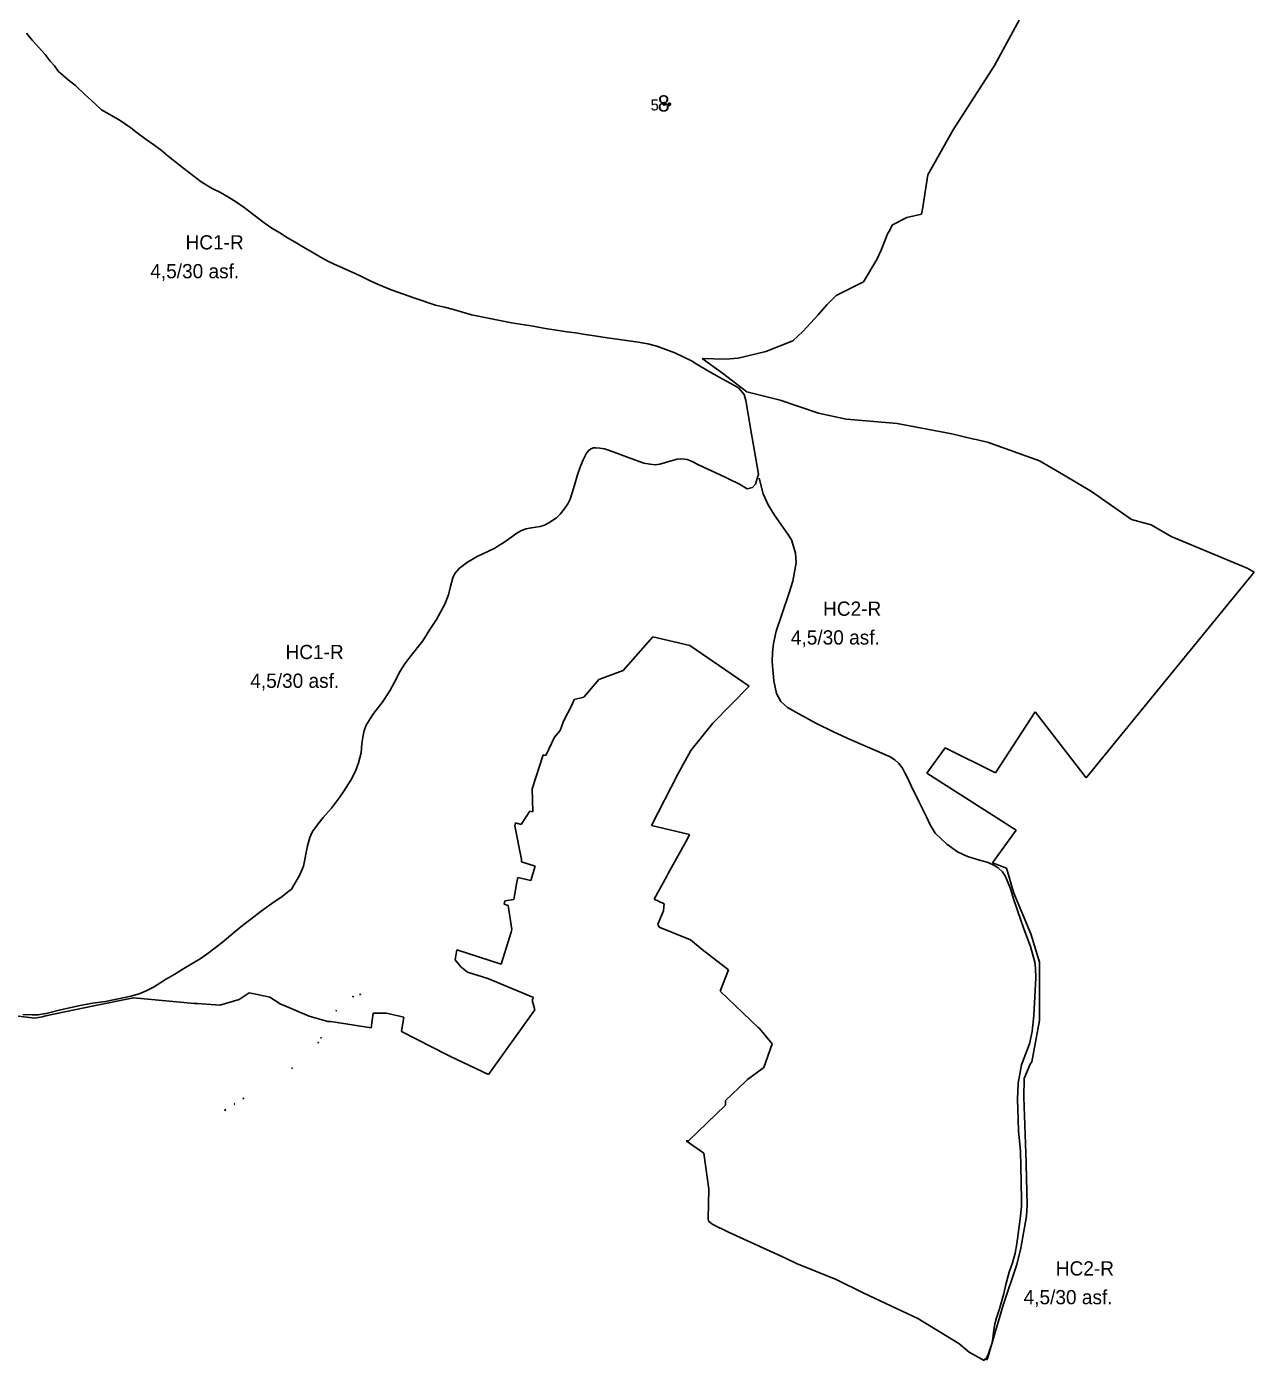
# Model space of a CAD drawing. Extents: x -543464 to -538545, y -1098769 to -1093672.
# Drawn here: x -540442 to -538545, y -1098552 to -1096492 of the extents above; entities that cross this region are included whole.
import ezdxf

# ---------------------------------------------------------------- set-up
doc = ezdxf.new("R2010")
doc.units = 0
for name, color, linetype in [('00_CHMI', 7, 'Continuous'), ('00_IGP_sondy', 7, 'Continuous'), ('01_OBVOD PÚ', 7, 'Continuous'), ('03_PC_NAVRH', 7, 'Continuous'), ('03_PC_POPIS_NAVRH', 7, 'Continuous'), ('07_VODOVOD', 7, 'Continuous')]:
    doc.layers.add(name, color=color, linetype=linetype)

msp = doc.modelspace()

# ---------------------------------------------------------------- linework, layer by layer
at = {"layer": '00_CHMI'}
for p, q in [((-539454.5, -1096611.1), (-539459.5, -1096611.1)), ((-539457, -1096613.5), (-539457, -1096608.8)), ((-539457, -1096611.1), (-539457, -1096611.1))]:
    msp.add_line(p, q, dxfattribs=at)
msp.add_circle((-539457, -1096611.1), 2, dxfattribs=at)
at = {"layer": '00_IGP_sondy'}
for p, q in [((-539446.6, -1096612), (-539451.6, -1096612)), ((-539449.1, -1096614.3), (-539449.1, -1096609.6)), ((-539449.1, -1096612), (-539449.1, -1096612))]:
    msp.add_line(p, q, dxfattribs=at)
msp.add_circle((-539449.1, -1096612), 2, dxfattribs=at)
at = {"layer": '01_OBVOD PÚ'}
for p, q in [((-538946.8, -1096551.9), (-538908.6, -1096482.2)), ((-539010.8, -1096651.4), (-538946.8, -1096551.9)), ((-539049.7, -1096721.1), (-539010.8, -1096651.4)), ((-539058.2, -1096773.9), (-539049.7, -1096721.1)), ((-539082.5, -1096786.7), (-539059.5, -1096781.4)), ((-539059.5, -1096781.4), (-539058.2, -1096773.9)), ((-539110.2, -1096808.8), (-539104.2, -1096797.9)), ((-539104.2, -1096797.9), (-539082.5, -1096786.7)), ((-539122.1, -1096837.3), (-539111.5, -1096811.1)), ((-539111.5, -1096811.1), (-539110.2, -1096808.8)), ((-539128.7, -1096851.5), (-539122.1, -1096837.3)), ((-539149.4, -1096885.9), (-539128.7, -1096851.5)), ((-539191.3, -1096907.2), (-539149.4, -1096885.9)), ((-539206.1, -1096921.4), (-539191.3, -1096907.2)), ((-539219.2, -1096936.8), (-539206.1, -1096921.4)), ((-539242.7, -1096962.7), (-539219.2, -1096936.8)), ((-539258.6, -1096977.3), (-539242.7, -1096962.7)), ((-539300, -1096993.8), (-539258.6, -1096977.3)), ((-539367, -1097027.2), (-539398.5, -1097004.4)), ((-539398.5, -1097004.4), (-539362.9, -1097005.6)), ((-539362.9, -1097005.6), (-539343, -1097004.1)), ((-539343, -1097004.1), (-539300, -1096993.8)), ((-539329.7, -1097056), (-539367, -1097027.2)), ((-539278.2, -1097068.7), (-539329.7, -1097056)), ((-539218.5, -1097088.8), (-539278.2, -1097068.7)), ((-539176.1, -1097098), (-539218.5, -1097088.8)), ((-539169.2, -1097098.9), (-539176.1, -1097098)), ((-539097.2, -1097104.9), (-539169.2, -1097098.9)), ((-539012.8, -1097120.8), (-539097.2, -1097104.9)), ((-538978.7, -1097128.8), (-539012.8, -1097120.8)), ((-538975.3, -1097129.6), (-538978.7, -1097128.8)), ((-538956.1, -1097134.1), (-538975.3, -1097129.6)), ((-538877.1, -1097162.4), (-538956.1, -1097134.1)), ((-538735.3, -1097253.1), (-538797.2, -1097209.7)), ((-538705, -1097261.1), (-538735.3, -1097253.1)), ((-538673.7, -1097279.6), (-538705, -1097261.1)), ((-538556.7, -1097328.1), (-538673.7, -1097279.6)), ((-538669.6, -1097486.2), (-538545.5, -1097334.4)), ((-538545.5, -1097334.4), (-538556.7, -1097328.1)), ((-539520.5, -1097486.2), (-539474.7, -1097434.5)), ((-539474.7, -1097434.5), (-539417.7, -1097447.8)), ((-539417.7, -1097447.8), (-539325.8, -1097510.3)), ((-539557.9, -1097500.1), (-539520.5, -1097486.2)), ((-538805.1, -1097652.1), (-538669.6, -1097486.2)), ((-539581, -1097527.5), (-539557.9, -1097500.1)), ((-539596.3, -1097530.9), (-539581, -1097527.5)), ((-539325.8, -1097510.3), (-539382.1, -1097567.6)), ((-539612.9, -1097564.4), (-539599.9, -1097539.6)), ((-539599.9, -1097539.6), (-539596.3, -1097530.9)), ((-539617.9, -1097579.2), (-539612.9, -1097564.4)), ((-539382.1, -1097567.6), (-539416, -1097609.7)), ((-538945.4, -1097644.3), (-538883.8, -1097550.2)), ((-538883.8, -1097550.2), (-538810.3, -1097645.3)), ((-539640.2, -1097617.5), (-539626.7, -1097589.2)), ((-539626.7, -1097589.2), (-539617.9, -1097579.2)), ((-539416, -1097609.7), (-539435.9, -1097646.6)), ((-539051.3, -1097644.6), (-539023.3, -1097605.5)), ((-539023.3, -1097605.5), (-538945.4, -1097644.3)), ((-539661.1, -1097668.9), (-539643.9, -1097616.4)), ((-539643.9, -1097616.4), (-539640.2, -1097617.5)), ((-539435.9, -1097646.6), (-539476.7, -1097725.6)), ((-538913.4, -1097733), (-539051.3, -1097644.6)), ((-538810.3, -1097645.3), (-538805.1, -1097652.1)), ((-539660.2, -1097704.7), (-539661.1, -1097668.9)), ((-539678.2, -1097724.2), (-539664.7, -1097703.4)), ((-539664.7, -1097703.4), (-539660.2, -1097704.7)), ((-539687.7, -1097726.1), (-539686.8, -1097721.3)), ((-539677.3, -1097777.9), (-539687.7, -1097726.1)), ((-539686.8, -1097721.3), (-539678.2, -1097724.2)), ((-539476.7, -1097725.6), (-539417.8, -1097739.7)), ((-538949.8, -1097783.5), (-538913.4, -1097733)), ((-539420.8, -1097745.2), (-539451.1, -1097799.9)), ((-539417.8, -1097739.7), (-539420.8, -1097745.2)), ((-539677.4, -1097782), (-539677.3, -1097777.9)), ((-539656.6, -1097788.7), (-539677.4, -1097782)), ((-539663.3, -1097810.6), (-539656.6, -1097788.7)), ((-538928.2, -1097791.6), (-538949.8, -1097783.5)), ((-538926.8, -1097796.5), (-538928.2, -1097791.6)), ((-539689.2, -1097839.9), (-539684.8, -1097813.1)), ((-539684.8, -1097813.1), (-539683.1, -1097806)), ((-539683.1, -1097806), (-539663.3, -1097810.6)), ((-539453.2, -1097803.8), (-539472.8, -1097839.3)), ((-539451.1, -1097799.9), (-539453.2, -1097803.8)), ((-538917.2, -1097830.2), (-538926.8, -1097796.5)), ((-538890.6, -1097892.9), (-538917.2, -1097830.2)), ((-539704.1, -1097847), (-539703.5, -1097841.9)), ((-539698.3, -1097849.4), (-539704.1, -1097847)), ((-539703.5, -1097841.9), (-539689.2, -1097839.9)), ((-539692.3, -1097886.3), (-539698.3, -1097849.4)), ((-539472.8, -1097839.3), (-539457.3, -1097846.8)), ((-539457.6, -1097851), (-539458, -1097857.2)), ((-539457.3, -1097846.8), (-539457.6, -1097851)), ((-539458, -1097857.2), (-539466.8, -1097877.9)), ((-539708.8, -1097939.7), (-539693.5, -1097890.2)), ((-539693.5, -1097890.2), (-539692.3, -1097886.3)), ((-539466.8, -1097877.9), (-539465, -1097882.7)), ((-539465, -1097882.7), (-539416.6, -1097902.1)), ((-538877.1, -1097936.9), (-538890.6, -1097892.9)), ((-539780.2, -1097933), (-539777.3, -1097917.9)), ((-539777.3, -1097917.9), (-539708.8, -1097939.7)), ((-539416.6, -1097902.1), (-539398.4, -1097917.3)), ((-539398.4, -1097917.3), (-539358, -1097948.6)), ((-539771.4, -1097944.1), (-539780.2, -1097933)), ((-538877.3, -1098026.7), (-538877.1, -1097936.9)), ((-539761.2, -1097952), (-539771.4, -1097944.1)), ((-539729.6, -1097961.9), (-539761.2, -1097952)), ((-539358, -1097948.6), (-539370.8, -1097981.4)), ((-539659.1, -1097991.5), (-539729.6, -1097961.9)), ((-540338.2, -1098004.2), (-540276.8, -1097991.9)), ((-540276.8, -1097991.9), (-540182.9, -1098000.4)), ((-540182.9, -1098000.4), (-540178.1, -1098000.6)), ((-540178.1, -1098000.6), (-540143.4, -1098003.2)), ((-540143.4, -1098003.2), (-540113.6, -1097994.1)), ((-540113.6, -1097994.1), (-540098.1, -1097984.3)), ((-540098.1, -1097984.3), (-540085.5, -1097986.8)), ((-540085.5, -1097986.8), (-540083.5, -1097987.2)), ((-540083.5, -1097987.2), (-540066.4, -1097990.7)), ((-540066.4, -1097990.7), (-540050.4, -1098001)), ((-540050.4, -1098001), (-540005.7, -1098019.9)), ((-539661.1, -1097995.2), (-539659.1, -1097991.5)), ((-539657.1, -1098010.2), (-539661.1, -1097995.2)), ((-539370.8, -1097981.4), (-539311.9, -1098037.5)), ((-540471.6, -1098018), (-540429.4, -1098023.4)), ((-540429.4, -1098023.4), (-540418.1, -1098021)), ((-540418.1, -1098021), (-540410.1, -1098019.3)), ((-540410.1, -1098019.3), (-540338.2, -1098004.2)), ((-540005.7, -1098019.9), (-539976.6, -1098028.4)), ((-539909.8, -1098038.1), (-539906.9, -1098015.4)), ((-539906.9, -1098015.4), (-539886.1, -1098015.3)), ((-539886.1, -1098015.3), (-539859.5, -1098021.7)), ((-539859.5, -1098021.7), (-539863.1, -1098043.7)), ((-539728.4, -1098110.3), (-539657.1, -1098010.2)), ((-539971.9, -1098028.5), (-539909.8, -1098038.1)), ((-539311.9, -1098037.5), (-539309.9, -1098038.9)), ((-539309.9, -1098038.9), (-539290.1, -1098062.6)), ((-538889.4, -1098090.5), (-538877.3, -1098026.7)), ((-539863.1, -1098043.7), (-539792.5, -1098080)), ((-539290.1, -1098062.6), (-539303.4, -1098099.5)), ((-539792.5, -1098080), (-539787.1, -1098082.6)), ((-539787.1, -1098082.6), (-539728.4, -1098110.3)), ((-539303.4, -1098099.5), (-539328.3, -1098117.7)), ((-538901, -1098116.5), (-538891.8, -1098094.1)), ((-538891.8, -1098094.1), (-538889.4, -1098090.5)), ((-539331.1, -1098120.3), (-539362.4, -1098150.3)), ((-539328.3, -1098117.7), (-539331.1, -1098120.3)), ((-538901.3, -1098145.3), (-538901, -1098116.5)), ((-538898.1, -1098245.9), (-538901.3, -1098145.3)), ((-539362.6, -1098157.7), (-539419.2, -1098211.9)), ((-539362.4, -1098150.3), (-539362.6, -1098157.7)), ((-539419.2, -1098211.9), (-539423.4, -1098212.6)), ((-539423.4, -1098212.6), (-539396.1, -1098231.6)), ((-539396.1, -1098231.6), (-539388.4, -1098287)), ((-538898.1, -1098249.4), (-538898.1, -1098245.9)), ((-538896.4, -1098312.1), (-538898.1, -1098249.4)), ((-539388.4, -1098287), (-539389.3, -1098332.6)), ((-538906, -1098378.3), (-538897.3, -1098328.9)), ((-538897.3, -1098328.9), (-538896.4, -1098312.1)), ((-539389.3, -1098332.6), (-539388.9, -1098336.9)), ((-539388.9, -1098336.9), (-539381.9, -1098341.6)), ((-539381.9, -1098341.6), (-539357.7, -1098353.8)), ((-539357.7, -1098353.8), (-539269.6, -1098393.6)), ((-538912.2, -1098403.5), (-538906, -1098378.3)), ((-539269.6, -1098393.6), (-539252.7, -1098401.9)), ((-539252.7, -1098401.9), (-539191.5, -1098426.9)), ((-538933.5, -1098466.4), (-538912.2, -1098403.5)), ((-539191.5, -1098426.9), (-539148.6, -1098448.1)), ((-539148.6, -1098448.1), (-539065.3, -1098486.9)), ((-538957.7, -1098548.6), (-538933.5, -1098466.4)), ((-539065.3, -1098486.9), (-539002.2, -1098525.6)), ((-539002.2, -1098525.6), (-538985.8, -1098539)), ((-538985.8, -1098539), (-538963, -1098551.6)), ((-538963, -1098551.6), (-538961.6, -1098549)), ((-538958.6, -1098550.7), (-538957.7, -1098548.6))]:
    msp.add_line(p, q, dxfattribs=at)
for points in [[(-538797.2, -1097209.7), (-538840.5, -1097184), (-538877.1, -1097162.4)], [(-539976.6, -1098028.4), (-539973.8, -1098028.5), (-539971.9, -1098028.5)], [(-538961.6, -1098549), (-538960, -1098549.9), (-538958.6, -1098550.7)]]:
    msp.add_lwpolyline(points, dxfattribs=at)
at = {"layer": '03_PC_NAVRH'}
for points in [[(-540442.4, -1096501.9), (-540433.2, -1096512.9), (-540413.3, -1096534.8), (-540405.8, -1096545.3), (-540399, -1096552.6), (-540393.1, -1096560.6), (-540377.7, -1096574.1), (-540366.6, -1096583.1), (-540351.6, -1096597.1), (-540342.5, -1096605.6), (-540326.5, -1096620.4), (-540307.3, -1096631.4), (-540297.6, -1096637), (-540281.1, -1096648.3), (-540271.2, -1096656), (-540257.3, -1096666.1), (-540245.3, -1096674.7), (-540234.4, -1096683), (-540223.6, -1096692.2), (-540199.1, -1096711.1), (-540172.4, -1096731.6), (-540155.2, -1096741.8), (-540142.4, -1096748), (-540130, -1096755.6), (-540117.6, -1096763.1), (-540106.1, -1096771.4), (-540090.7, -1096783.3), (-540075, -1096795), (-540063.3, -1096803.1), (-540050.7, -1096810.6), (-540039, -1096817.9), (-540027.2, -1096824.9), (-540015.5, -1096832), (-540003.5, -1096838.9), (-539986.8, -1096848.5), (-539974.6, -1096855.1), (-539962.1, -1096860.7), (-539949.2, -1096866.5), (-539927.6, -1096876.2), (-539910.3, -1096884.9), (-539897.3, -1096890.7), (-539878.7, -1096898.2), (-539842.2, -1096911.2), (-539810.2, -1096922), (-539796.6, -1096925.3), (-539782.5, -1096928.7), (-539754.6, -1096936.9), (-539726.2, -1096942.8), (-539692.9, -1096949.6), (-539659.5, -1096954.8), (-539640.9, -1096958.3), (-539627, -1096960.3), (-539607.4, -1096963.1), (-539593.6, -1096965.1), (-539579.1, -1096967.4), (-539564.7, -1096969.7), (-539545.4, -1096972.4), (-539526.1, -1096975.2), (-539511.7, -1096977.3), (-539497.2, -1096979.3), (-539482.5, -1096982), (-539468.3, -1096985.6), (-539454.7, -1096990.4), (-539440.9, -1096995.8), (-539427.8, -1097001.8), (-539414.8, -1097008.2), (-539407.5, -1097012.9), (-539388.7, -1097024.1), (-539372.4, -1097033.3), (-539355.2, -1097042.8), (-539342.4, -1097049.8), (-539333.4, -1097059.9), (-539331, -1097069.4), (-539327.3, -1097090.5), (-539323.1, -1097114.9), (-539319.7, -1097136), (-539311.5, -1097182.9), (-539316, -1097198.4)], [(-539316, -1097198.4), (-539320.6, -1097203.6), (-539328.7, -1097205.6), (-539340.6, -1097198.7), (-539357.7, -1097190.3), (-539364.2, -1097187.2), (-539389.5, -1097175.3), (-539405.1, -1097168.3), (-539414, -1097163.5), (-539421.4, -1097160.7), (-539430.1, -1097159.5), (-539437.1, -1097159.8), (-539446.1, -1097162.5), (-539464, -1097167.7), (-539471.1, -1097168.5), (-539479, -1097167.7), (-539488.4, -1097165.9), (-539498.1, -1097162.5), (-539511.1, -1097158), (-539531.7, -1097150.2), (-539541.4, -1097146.5), (-539549.3, -1097144), (-539556.3, -1097142.9), (-539562.7, -1097142.3), (-539566.1, -1097142.6), (-539570.3, -1097144), (-539573.7, -1097146.5), (-539577.1, -1097150.9), (-539582.3, -1097161), (-539586.2, -1097170.8), (-539590.9, -1097184.2), (-539595.7, -1097200.2), (-539599.2, -1097211.9), (-539602.6, -1097221.6), (-539606, -1097229), (-539611.4, -1097237.1), (-539618, -1097244.8), (-539623.4, -1097250.3), (-539635.4, -1097258.3), (-539641.9, -1097261.7), (-539648.9, -1097263.9), (-539662, -1097265.8), (-539671, -1097267.5), (-539678.5, -1097270.5), (-539686.3, -1097275.1), (-539692.6, -1097280), (-539706.3, -1097289.9), (-539712.4, -1097293.5), (-539718.5, -1097297.2), (-539728.5, -1097301.9), (-539745.8, -1097310.1), (-539760.9, -1097319.1), (-539765.2, -1097321.9), (-539773.1, -1097328.1), (-539780.3, -1097336.5), (-539783.7, -1097343.4), (-539787, -1097356.4), (-539790.2, -1097369.4), (-539796.1, -1097383.9), (-539808.9, -1097407.4), (-539818.9, -1097423), (-539830.1, -1097440.5), (-539850.2, -1097465.7), (-539857.9, -1097476), (-539865.1, -1097487.4), (-539873.8, -1097504.5), (-539881.1, -1097517.9), (-539892.9, -1097535.5), (-539901.8, -1097547.3), (-539907.2, -1097554.4), (-539917.4, -1097570.6), (-539920.8, -1097578.9), (-539922.8, -1097589.2), (-539924.1, -1097599.6), (-539925.2, -1097613.2), (-539929.3, -1097629), (-539934.1, -1097641.8), (-539941.1, -1097655.4), (-539952, -1097672.8), (-539958.7, -1097682.6), (-539971.2, -1097698.9), (-539983.7, -1097713.4), (-539991.5, -1097722.9), (-540000.2, -1097735.1), (-540004.5, -1097744.3), (-540008.2, -1097757.1), (-540014.5, -1097788.6), (-540020.3, -1097803), (-540033, -1097823.9), (-540037.2, -1097827.2), (-540049.2, -1097836.6), (-540059.5, -1097843.6), (-540079.8, -1097858.2), (-540095.6, -1097870.2), (-540108.7, -1097880.2), (-540120.1, -1097889.6), (-540140.1, -1097906.2), (-540163.7, -1097924.1), (-540174.1, -1097931.5), (-540199.1, -1097946.7), (-540213.2, -1097955.2), (-540227.3, -1097963.7), (-540246.2, -1097975.1), (-540257.4, -1097981.1), (-540268.3, -1097985.6), (-540281.2, -1097989.2), (-540298.2, -1097992.7), (-540320.4, -1097997.2), (-540340.3, -1098000.2), (-540359.2, -1098003.5), (-540389.8, -1098010.3), (-540409.8, -1098015.4), (-540415.3, -1098016.7), (-540424.7, -1098018.1), (-540433.7, -1098018.2), (-540448.1, -1098017.5)], [(-539310.6, -1097189.5), (-539304.2, -1097213.6), (-539296.6, -1097230.6), (-539286.9, -1097246.6), (-539265.9, -1097275.9), (-539260.6, -1097284.7), (-539258.3, -1097291.1), (-539254.4, -1097305), (-539253.1, -1097320), (-539258.2, -1097348.2), (-539263.9, -1097366.2), (-539274.9, -1097398.5), (-539283.9, -1097425.6), (-539288.5, -1097444.8), (-539290, -1097458.6), (-539290.3, -1097472.9), (-539287.9, -1097502.1), (-539283.7, -1097521.6), (-539277, -1097534), (-539266.6, -1097543.4), (-539249.1, -1097553.3), (-539222.8, -1097567.4), (-539195.8, -1097581), (-539169.6, -1097592.9), (-539124.7, -1097612.3), (-539111.7, -1097618), (-539108.1, -1097619.5), (-539100.8, -1097624.1), (-539094.5, -1097630), (-539089.1, -1097637.2), (-539084.7, -1097645.1), (-539080.9, -1097653), (-539072.8, -1097669.9), (-539066.5, -1097682.8), (-539062.8, -1097690.5), (-539051.8, -1097712.4), (-539046.1, -1097724.5), (-539038.5, -1097737.6), (-539020.6, -1097754.7), (-539003.8, -1097766.1), (-538988.6, -1097773.7), (-538970.2, -1097779.4), (-538958.2, -1097782.5), (-538953.6, -1097784.1), (-538949.1, -1097786.2), (-538941, -1097790.9), (-538934.4, -1097797.1), (-538929.8, -1097804.6), (-538926.1, -1097813.1), (-538922.9, -1097821.7), (-538920.2, -1097830.3), (-538917.4, -1097838.8), (-538911.2, -1097856.9), (-538901.3, -1097885.1), (-538891, -1097912.7), (-538884.6, -1097936.5), (-538883.3, -1097946.1), (-538882.8, -1097960.9), (-538883.8, -1097980.2), (-538886.3, -1098019.2), (-538888.5, -1098043.8), (-538892.6, -1098062.8), (-538905.2, -1098095), (-538910.2, -1098123.8), (-538911.1, -1098149), (-538910.1, -1098178.9), (-538909.6, -1098197.7), (-538906.9, -1098228), (-538906.1, -1098252.6), (-538905.6, -1098276.1), (-538905, -1098304.9), (-538905.1, -1098314.2), (-538907.1, -1098333.1), (-538912.2, -1098371.7), (-538914.8, -1098386.2), (-538919.2, -1098401.2), (-538924, -1098415.2), (-538929.2, -1098434.3), (-538932.2, -1098448.4), (-538939.2, -1098471.9), (-538944, -1098485.8), (-538946.1, -1098495.3), (-538948.3, -1098508.8), (-538949.5, -1098517.7), (-538951.2, -1098526.2), (-538954.1, -1098534.9), (-538957.4, -1098543.9), (-538960, -1098549.9)]]:
    msp.add_lwpolyline(points, dxfattribs=at)
at = {"layer": '07_VODOVOD'}
for points in [[(-539937.8, -1097989.4), (-539938.3, -1097989.6), (-539938, -1097990.2), (-539937.5, -1097990), (-539937.8, -1097989.4)], [(-539926.5, -1097985.9), (-539927, -1097986.1), (-539926.8, -1097986.7), (-539926.3, -1097986.6), (-539926.5, -1097985.9)], [(-539963.9, -1098011.1), (-539964.3, -1098011.5), (-539963.8, -1098012), (-539963.4, -1098011.6), (-539963.9, -1098011.1)], [(-539991.5, -1098060.6), (-539991.9, -1098061), (-539991.4, -1098061.4), (-539991, -1098061), (-539991.5, -1098060.6)], [(-539987.4, -1098053.2), (-539987.7, -1098053.6), (-539987.1, -1098054), (-539986.8, -1098053.5), (-539987.4, -1098053.2)], [(-540031.9, -1098100), (-540032.4, -1098100.3), (-540032, -1098100.9), (-540031.5, -1098100.6), (-540031.9, -1098100)], [(-540136.2, -1098165.2), (-540135.2, -1098164.2), (-540134.6, -1098164.8), (-540135.5, -1098165.8), (-540136.2, -1098165.2)], [(-540120.7, -1098155.3), (-540121.2, -1098155.6), (-540120.8, -1098156.1), (-540120.4, -1098155.8), (-540120.7, -1098155.3)], [(-540107, -1098146.6), (-540107.5, -1098146.9), (-540107.1, -1098147.5), (-540106.6, -1098147.2), (-540107, -1098146.6)]]:
    msp.add_lwpolyline(points, dxfattribs=at)

# ---------------------------------------------------------------- texts
at = {"layer": '00_CHMI'}
msp.add_text('5', height=17, dxfattribs=at).set_placement((-539478.1, -1096621.5))
at = {"layer": '00_IGP_sondy'}
msp.add_text('8', height=25, dxfattribs=at).set_placement((-539467.2, -1096623.1))
at = {"layer": '03_PC_POPIS_NAVRH'}
for s, p in [('HC1-R', (-540196.5, -1096836.1)), ('4,5/30 asf.', (-540251, -1096880.6)), ('HC2-R', (-539211.7, -1097401.8)), ('4,5/30 asf.', (-539261.4, -1097446.2)), ('HC1-R', (-540042.1, -1097468.7)), ('4,5/30 asf.', (-540096.5, -1097513.1)), ('HC2-R', (-538852.2, -1098420.6)), ('4,5/30 asf.', (-538901.9, -1098465))]:
    msp.add_text(s, height=22, dxfattribs=at).set_placement(p)

doc.saveas('drawing.dxf')
